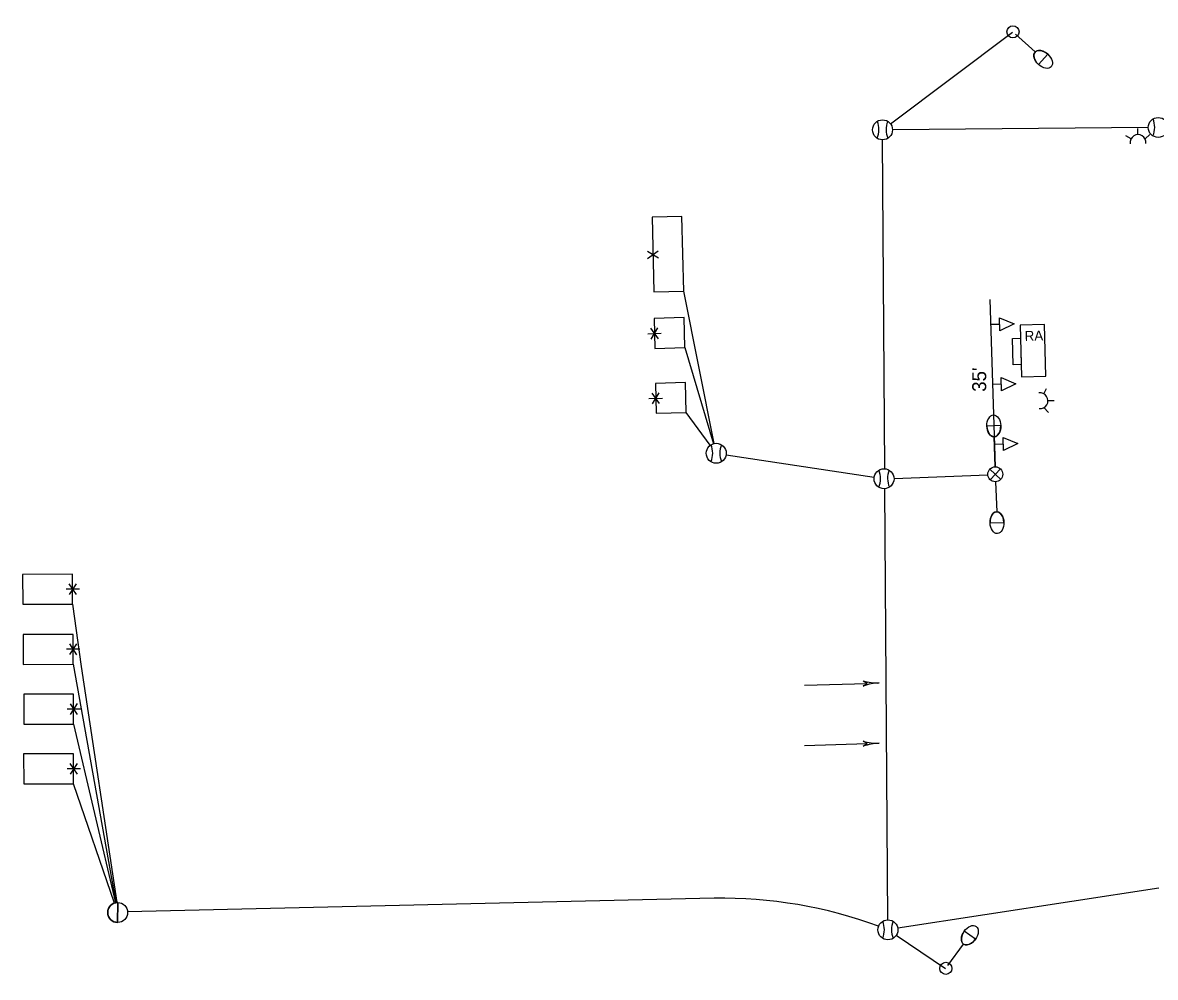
# Model space of a CAD drawing. Extents: x 596176 to 605330, y 332416 to 402398.
# Drawn here: x 603804 to 604030.9, y 339261.8 to 339453.1 of the extents above; entities that cross this region are included whole.
import ezdxf

# ---------------------------------------------------------------- set-up
doc = ezdxf.new("R2010")
doc.units = 0
for name, color, linetype in [('P_LTG', 7, 'Continuous'), ('P_SIG', 7, 'Continuous'), ('P_SIG_Bold', 7, 'Continuous'), ('P_SIG_Conduit', 7, 'Continuous'), ('P_SIG_Loops', 7, 'Continuous')]:
    doc.layers.add(name, color=color, linetype=linetype)

# ---------------------------------------------------------------- blocks, each defined once
blk = doc.blocks.new('LUMINAIRES')
at = {"layer": 'P_LTG'}
for p, q in [((4.32, 25.12), (-4.14, 25.12)), ((0.05, 2.3), (0.05, 18.44))]:
    blk.add_line(p, q, dxfattribs=at)
blk.add_circle((0.05, 0.15), 3.68, dxfattribs=at)
blk.add_ellipse((0.09, 25.12), major_axis=(0, 6.65), ratio=0.636439, dxfattribs=at)
blk.add_ellipse((0.09, 25.12), major_axis=(0, 6.65), ratio=0.636439, start_param=1.570796, end_param=4.712389, dxfattribs=at)

msp = doc.modelspace()

# ---------------------------------------------------------------- linework, layer by layer
at = {"layer": 'P_LTG'}
for p, q in [((603999.95, 339372.35), (603997.17, 339372.26)), ((603998.8, 339364.11), (603998.61, 339370.17)), ((603998.9, 339361.11), (603999.13, 339355.11)), ((603997.81, 339352.87), (604000.58, 339352.97))]:
    msp.add_line(p, q, dxfattribs=at)
for centre, major_axis in [((603998.56, 339372.3), (-0.07, 2.18)), ((603999.19, 339352.92), (0.08, -2.18))]:
    msp.add_ellipse(centre, major_axis=major_axis, ratio=0.636439, dxfattribs=at)
for centre, major_axis in [((603998.56, 339372.3), (-0.07, 2.18)), ((603999.19, 339352.92), (0.08, -2.18))]:
    msp.add_ellipse(centre, major_axis=major_axis, ratio=0.636439, start_param=1.570796, end_param=4.712389, dxfattribs=at)
at = {"layer": 'P_SIG'}
for p, q in [((604026.07, 339429.8), (604024.99, 339430.39)), ((604027.44, 339430.63), (604027.43, 339431.86)), ((604028.86, 339429.8), (604029.84, 339430.69)), ((603999.71, 339392.64), (603997.94, 339392.59)), ((604000.04, 339380.65), (603998.27, 339380.59)), ((604008.55, 339378.74), (604009.13, 339379.82)), ((604008.58, 339375.95), (604009.48, 339374.98)), ((604009.4, 339377.38), (604010.63, 339377.4)), ((604000.43, 339368.65), (603998.66, 339368.6)), ((603960.61, 339320.33), (603973.18, 339320.72)), ((603960.61, 339308.25), (603973.18, 339308.64)), ((603823.03, 339276.82), (603823.01, 339272.82))]:
    msp.add_line(p, q, dxfattribs=at)
for points in [[(604002.66, 339392.73), (603999.74, 339391.32), (603999.67, 339393.96)], [(604008.95, 339382.26), (604008.68, 339392.61), (604003.86, 339392.48), (604004.13, 339382.14)], [(604002.3, 339389.82), (604003.89, 339389.86), (604004.03, 339384.59), (604002.44, 339384.54)], [(604003, 339380.73), (604000.08, 339379.33), (604000, 339381.96)], [(604003.39, 339368.74), (604000.47, 339367.34), (604000.4, 339369.97)]]:
    msp.add_lwpolyline(points, close=True, dxfattribs=at)
for points in [[(603972.4, 339320.19), (603973.18, 339320.72), (603972.37, 339321.19)], [(603972.4, 339308.12), (603973.18, 339308.64), (603972.37, 339309.12)], [(603823.01, 339272.82), (603823.03, 339276.82)]]:
    msp.add_lwpolyline(points, dxfattribs=at)
for centre in [(603976.26, 339431.6), (604031.5, 339432.08), (603942.94, 339366.81), (603976.56, 339361.71), (603823.02, 339274.82), (603977.34, 339271.35)]:
    msp.add_circle(centre, 2, dxfattribs=at)
for centre, radius, start, end in [((603971.19, 339431.64), 4.36, 336.6741, 22.5272), ((603981.33, 339431.64), 4.36, 157.5751, 203.4282), ((604026.43, 339432.12), 4.36, 336.6741, 22.5272), ((604027.46, 339429.06), 1.58, 352.7774, 188.2849), ((604007.83, 339377.34), 1.58, 263.3712, 98.8787), ((603937.87, 339366.85), 4.36, 336.6741, 22.5272), ((603948.01, 339366.86), 4.36, 157.5751, 203.4282), ((603971.49, 339361.74), 4.36, 336.6741, 22.5272), ((603981.63, 339361.75), 4.36, 157.5751, 203.4282), ((603975.26, 339331.28), 10.49, 254.0031, 271.7654), ((603975.9, 339310.31), 10.49, 91.7654, 109.5278), ((603975.26, 339319.2), 10.49, 254.0031, 271.7654), ((603975.9, 339298.23), 10.49, 91.7654, 109.5278), ((603823.02, 339274.82), 2, 89.7008, 180), ((603823.02, 339274.82), 2, 180, 269.7008), ((603972.27, 339271.39), 4.36, 336.6741, 22.5272), ((603982.41, 339271.4), 4.36, 157.5751, 203.4282)]:
    msp.add_arc(centre, radius, start, end, dxfattribs=at)
at = {"layer": 'P_SIG_Bold'}
for p, q in [((603997.73, 339397.59), (603998.8, 339364.11)), ((603999.94, 339361.58), (603997.75, 339363.64)), ((603999.87, 339363.7), (603997.82, 339361.51))]:
    msp.add_line(p, q, dxfattribs=at)
msp.add_circle((603998.84, 339362.61), 1.5, dxfattribs=at)
at = {"layer": 'P_SIG_Conduit'}
for p, q in [((603977.86, 339432.8), (604002.3, 339451.18)), ((604031.59, 339279.68), (603979.32, 339271.66)), ((603979.02, 339270.27), (603988.9, 339263.62))]:
    msp.add_line(p, q, dxfattribs=at)
for points in [[(604029.5, 339432.07), (603978.26, 339431.61)], [(603976.71, 339363.7), (603976.26, 339429.6)], [(603944.92, 339366.51), (603974.58, 339362.01)], [(603978.56, 339361.78), (603997.35, 339362.5)], [(603977.33, 339273.35), (603976.74, 339359.71)], [(603942.54, 339277.67), (603825.01, 339274.95)]]:
    msp.add_lwpolyline(points, dxfattribs=at)
msp.add_arc((603944.03, 339186.98), 90.7, 69.7206, 90.9411, dxfattribs=at)
at = {"layer": 'P_SIG_Loops'}
for p, q in [((603933.08, 339414.2), (603930.08, 339414.12)), ((603929.15, 339407.31), (603931.36, 339405.96)), ((603929.2, 339405.86), (603931.33, 339407.35)), ((603930.22, 339407.99), (603930.29, 339405.32)), ((603942.55, 339368.77), (603936.46, 339399.28)), ((603931.35, 339389.75), (603929.86, 339391.88)), ((603929.9, 339389.7), (603931.25, 339391.91)), ((603929.22, 339390.77), (603931.89, 339390.84)), ((603930.59, 339390.82), (603930.67, 339387.82)), ((603936.66, 339387.98), (603942.37, 339368.73)), ((603929.47, 339377.77), (603932.15, 339377.83)), ((603931.6, 339376.75), (603930.12, 339378.88)), ((603930.15, 339376.7), (603931.5, 339378.91)), ((603930.84, 339377.82), (603930.92, 339374.82)), ((603941.75, 339368.42), (603936.92, 339374.97)), ((603815.36, 339339.58), (603812.68, 339339.58)), ((603813.25, 339340.66), (603814.68, 339338.49)), ((603814.7, 339340.67), (603813.3, 339338.5)), ((603813.99, 339336.57), (603815.73, 339324.07)), ((603813.34, 339328.63), (603814.77, 339326.46)), ((603814.79, 339328.65), (603813.39, 339326.47)), ((603815.44, 339327.56), (603812.77, 339327.56)), ((603814.07, 339324.54), (603822.66, 339276.79)), ((603815.73, 339324.07), (603822.82, 339276.81)), ((603813.47, 339316.65), (603814.9, 339314.47)), ((603814.92, 339316.66), (603813.51, 339314.49)), ((603815.57, 339315.57), (603812.9, 339315.57)), ((603814.2, 339312.55), (603822.56, 339276.77)), ((603815.56, 339303.61), (603812.88, 339303.61)), ((603813.45, 339304.68), (603814.88, 339302.51)), ((603814.9, 339304.69), (603813.5, 339302.52)), ((603822.37, 339276.71), (603814.15, 339300.59))]:
    msp.add_line(p, q, dxfattribs=at)
for points in [[(603930.08, 339414.12), (603930.46, 339399.12), (603936.46, 339399.28), (603936.07, 339414.27)], [(603930.67, 339387.82), (603936.66, 339387.98), (603936.51, 339393.98), (603930.51, 339393.82)], [(603930.92, 339374.82), (603936.92, 339374.97), (603936.76, 339380.97), (603930.77, 339380.82)], [(603813.98, 339342.57), (603803.98, 339342.56), (603803.99, 339336.56), (603813.99, 339336.57)], [(603814.07, 339330.54), (603804.07, 339330.53), (603804.07, 339324.53), (603814.07, 339324.54)], [(603814.2, 339318.55), (603804.2, 339318.54), (603804.2, 339312.54), (603814.2, 339312.55)], [(603814.18, 339306.59), (603804.18, 339306.58), (603804.19, 339300.58), (603814.19, 339300.59)]]:
    msp.add_lwpolyline(points, close=True, dxfattribs=at)

# ---------------------------------------------------------------- block references
at = {"layer": 'P_SIG', "xscale": 0.32808333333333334}
for p, yscale, rotation in [((604002.37, 339451.29), 0.3280833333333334, -132.40949839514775), ((603988.91, 339263.6), 0.3280833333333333, -35.803054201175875)]:
    msp.add_blockref('LUMINAIRES', p, dxfattribs=dict(at, yscale=yscale, rotation=rotation))

# ---------------------------------------------------------------- texts
at = {"layer": 'P_SIG'}
msp.add_text('RA', height=2, rotation=1.5107, dxfattribs=at).set_placement((604004.76, 339389.31))
at = {"layer": 'P_SIG_Bold'}
msp.add_text("35'", height=2.8, rotation=90, dxfattribs=at).set_placement((603997.03, 339379.12))

doc.saveas('drawing.dxf')
